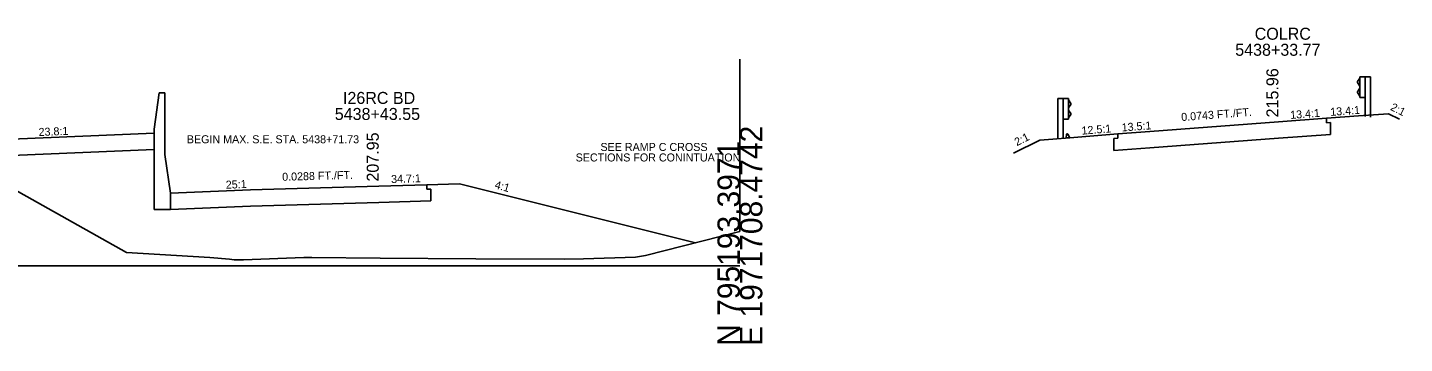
# Model space of a CAD drawing. Extents: x -161 to 1970889, y -4362 to 797231.
# Drawn here: x 1211 to 1383, y 4990.3 to 5029.7 of the extents above; entities that cross this region are included whole.
import ezdxf

# ---------------------------------------------------------------- set-up
doc = ezdxf.new("R2010")
doc.units = 0
for name, color, linetype in [('RD_GPK_XS_Cell', 7, 'Continuous'), ('RD_XS_Base', 7, 'Continuous'), ('RD_XS_CurbTop', 7, 'Continuous'), ('RD_XS_EarthShd', 7, 'Continuous'), ('RD_XS_ExGround', 7, 'Continuous'), ('RD_XS_GR', 7, 'Continuous'), ('RD_XS_MedBWall', 7, 'Continuous'), ('RD_XS_Pave', 7, 'Continuous'), ('RD_XS_PaveShd', 7, 'Continuous'), ('RD_XS_TieSlope', 7, 'Continuous'), ('RD_XS_TX_Elev_PR', 7, 'Continuous'), ('RD_XS_TX_Notes', 7, 'Continuous'), ('RD_XS_TX_Profile', 7, 'Continuous'), ('RD_XS_TX_ShdSlope', 7, 'Continuous'), ('RD_XS_TX_Slope', 7, 'Continuous'), ('RD_XS_TX_Station', 7, 'Continuous')]:
    doc.layers.add(name, color=color, linetype=linetype)

msp = doc.modelspace()

# ---------------------------------------------------------------- linework, layer by layer
at = {"layer": 'RD_GPK_XS_Cell'}
msp.add_line((1150, 5000), (1300, 5000), dxfattribs=at)
at = {"layer": 'RD_XS_Base'}
for p, q in [((1373.28, 5017.85), (1373.28, 5018.41)), ((1373.78, 5017.88), (1373.28, 5017.85)), ((1373.78, 5016.4), (1373.78, 5017.88)), ((1346.72, 5015.87), (1347.22, 5015.91)), ((1347.22, 5015.91), (1347.22, 5016.47)), ((1351.23, 5014.73), (1367.27, 5015.92)), ((1367.27, 5015.92), (1373.78, 5016.4)), ((1209, 5013.76), (1226.81, 5014.51)), ((1346.72, 5014.39), (1346.72, 5015.87)), ((1351.23, 5014.73), (1346.72, 5014.39)), ((1228.85, 5008.52), (1228.85, 5009.08)), ((1260.88, 5009.56), (1260.88, 5010.12)), ((1261.38, 5009.57), (1260.88, 5009.56)), ((1261.38, 5008.09), (1261.38, 5009.57)), ((1238.86, 5007.44), (1228.85, 5007.04)), ((1238.86, 5007.44), (1254.88, 5007.91)), ((1254.88, 5007.91), (1261.38, 5008.09))]:
    msp.add_line(p, q, dxfattribs=at)
at = {"layer": 'RD_XS_CurbTop'}
for p, q in [((1340.74, 5015.95), (1340.8, 5016.39)), ((1341.21, 5015.99), (1340.74, 5015.95)), ((1341.21, 5015.99), (1340.96, 5016.44))]:
    msp.add_line(p, q, dxfattribs=at)
msp.add_ellipse((1340.89, 5016.36), major_axis=(0, 0.131), ratio=0.686, start_param=5.388101, end_param=7.661995, dxfattribs=at)
at = {"layer": 'RD_XS_EarthShd'}
for p, q in [((1373.28, 5018.41), (1377.29, 5018.71)), ((1347.22, 5016.47), (1341.21, 5015.99)), ((1260.88, 5010.12), (1264.96, 5010.24))]:
    msp.add_line(p, q, dxfattribs=at)
at = {"layer": 'RD_XS_ExGround'}
msp.add_lwpolyline([(1209.2, 5009.59), (1223.35, 5001.64), (1233.79, 5001.02), (1236.24, 5000.82), (1236.83, 5000.76), (1237.98, 5000.73), (1245.53, 5001.04), (1245.92, 5001.03), (1246.54, 5001.02), (1255.05, 5000.97), (1267, 5000.88), (1278.1, 5000.81), (1280.45, 5000.85), (1286.94, 5001.09), (1288.21, 5001.29), (1300, 5004.26)], dxfattribs=at)
at = {"layer": 'RD_XS_GR'}
for p, q in [((1377.44, 5023.42), (1377.17, 5022.98)), ((1377.17, 5022.98), (1377.17, 5022.87)), ((1377.17, 5022.87), (1377.44, 5022.43)), ((1377.44, 5023.58), (1378.1, 5023.58)), ((1377.44, 5021.01), (1377.44, 5023.58)), ((1378.1, 5023.58), (1378.77, 5023.58)), ((1378.1, 5023.58), (1378.1, 5018.64)), ((1378.77, 5023.58), (1378.77, 5018.53)), ((1377.17, 5021.72), (1377.44, 5022.16)), ((1377.17, 5021.61), (1377.17, 5021.72)), ((1377.44, 5021.17), (1377.17, 5021.61)), ((1340.39, 5020.86), (1339.73, 5020.86)), ((1339.73, 5020.86), (1339.73, 5015.81)), ((1341.06, 5020.86), (1340.39, 5020.86)), ((1340.39, 5020.86), (1340.39, 5015.92)), ((1341.06, 5018.29), (1341.06, 5020.86)), ((1341.06, 5020.7), (1341.33, 5020.26)), ((1341.33, 5020.15), (1341.06, 5019.71)), ((1341.33, 5019), (1341.06, 5019.44)), ((1341.33, 5020.26), (1341.33, 5020.15)), ((1377.44, 5021.01), (1378.1, 5021.01)), ((1341.06, 5018.29), (1340.39, 5018.29)), ((1341.06, 5018.45), (1341.33, 5018.89)), ((1341.33, 5018.89), (1341.33, 5019))]:
    msp.add_line(p, q, dxfattribs=at)
at = {"layer": 'RD_XS_MedBWall'}
for p, q in [((1226.81, 5017.06), (1227.47, 5021.6)), ((1228.14, 5021.6), (1227.47, 5021.6)), ((1228.14, 5021.6), (1228.14, 5013.91)), ((1226.81, 5017.06), (1226.81, 5007.04)), ((1228.85, 5009.08), (1228.14, 5013.91)), ((1228.85, 5009.08), (1228.85, 5007.04)), ((1228.85, 5007.04), (1226.81, 5007.04))]:
    msp.add_line(p, q, dxfattribs=at)
at = {"layer": 'RD_XS_Pave'}
for p, q in [((1351.23, 5016.77), (1367.27, 5017.96)), ((1238.86, 5009.48), (1254.88, 5009.95))]:
    msp.add_line(p, q, dxfattribs=at)
at = {"layer": 'RD_XS_PaveShd'}
for p, q in [((1367.27, 5017.96), (1373.28, 5018.41)), ((1209, 5015.8), (1226.84, 5016.55)), ((1351.23, 5016.77), (1347.22, 5016.47)), ((1238.86, 5009.48), (1228.85, 5009.08)), ((1254.88, 5009.95), (1260.88, 5010.12))]:
    msp.add_line(p, q, dxfattribs=at)
at = {"layer": 'RD_XS_TieSlope'}
for p, q in [((1377.29, 5018.71), (1381.04, 5018.98)), ((1381.04, 5018.98), (1382.41, 5018.3)), ((1341.21, 5015.99), (1337.46, 5015.69)), ((1337.46, 5015.69), (1334.19, 5014.06)), ((1264.96, 5010.24), (1294.45, 5002.86))]:
    msp.add_line(p, q, dxfattribs=at)
at = {"layer": 'RD_XS_TX_Notes'}
msp.add_line((1300, 5004.26), (1300, 5025.79), dxfattribs=at)

# ---------------------------------------------------------------- texts
at = {"layer": 'RD_GPK_XS_Cell'}
for s, p in [('E 1971708.4742', (1302.8, 4990)), ('N 795193.3971', (1300, 4990))]:
    msp.add_text(s, height=2.8, rotation=90, dxfattribs=at).set_placement(p)
at = {"layer": 'RD_XS_TX_Elev_PR'}
for s, p in [(' 215.96', (1367.27, 5017.96)), (' 207.95', (1254.88, 5009.95))]:
    msp.add_text(s, height=1.5, rotation=90, dxfattribs=at).set_placement(p)
at = {"layer": 'RD_XS_TX_Notes'}
msp.add_text('BEGIN MAX. S.E. STA. 5438+71.73', height=1, dxfattribs=at).set_placement((1230.91, 5015.29))
for s, p in [('SEE RAMP C CROSS ', (1282.58, 5014.33)), ('SECTIONS FOR CONINTUATION', (1279.48, 5013.02))]:
    msp.add_text(s, height=1, rotation=360, dxfattribs=at).set_placement(p)
at = {"layer": 'RD_XS_TX_Profile'}
for s, rotation, p in [('23.8:1', 2.405, (1212.41, 5016.19)), ('34.7:1', 1.6506, (1256.44, 5010.32))]:
    msp.add_text(s, height=1, rotation=rotation, dxfattribs=at).set_placement(p)
at = {"layer": 'RD_XS_TX_ShdSlope'}
for s, rotation, p in [('13.4:1', 4.2525, (1373.79, 5018.7)), ('12.5:1', 4.5631, (1342.72, 5016.36))]:
    msp.add_text(s, height=1, rotation=rotation, dxfattribs=at).set_placement(p)
at = {"layer": 'RD_XS_TX_Slope'}
for s, rotation, p in [('0.0743 FT./FT.', 4.252, (1355.17, 5018.06)), ('13.4:1', 4.2525, (1368.78, 5018.32)), ('2:1', 333.435, (1381.17, 5019.48)), ('13.5:1', 4.252, (1347.73, 5016.76)), ('2:1', 26.565, (1334.6, 5014.92)), ('0.0288 FT./FT.', 1.6505, (1242.83, 5010.6)), ('25:1', 2.2876, (1235.79, 5009.61)), ('4:1', 344.1175, (1269.29, 5009.69))]:
    msp.add_text(s, height=1, rotation=rotation, dxfattribs=at).set_placement(p)
at = {"layer": 'RD_XS_TX_Station'}
for s, p in [('COLRC', (1364.31, 5028.21)), ('5438+33.77', (1361.88, 5026.21)), ('I26RC BD', (1250.41, 5020.2)), ('5438+43.55', (1249.39, 5018.2))]:
    msp.add_text(s, height=1.5, dxfattribs=at).set_placement(p)

doc.saveas('drawing.dxf')
